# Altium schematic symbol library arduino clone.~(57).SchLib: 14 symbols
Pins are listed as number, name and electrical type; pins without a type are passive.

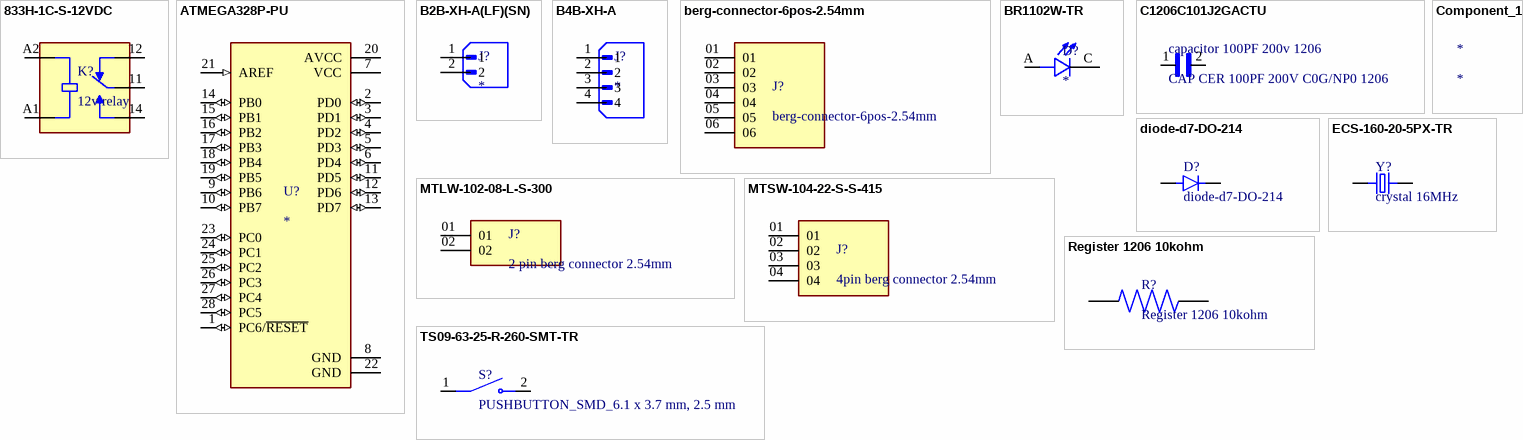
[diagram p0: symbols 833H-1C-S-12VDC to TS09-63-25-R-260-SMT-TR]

## 833H-1C-S-12VDC
designator K?, comment 12v relay
833H Series 10 A SPDT 12 VDC Through Hole Miniature Sugar Cube Power Relay; MF: Song Chuan; MP: 833H-1C-S-12VDC
footprint RELAY_833H-1C-S-12VDC
pins: 11 COM, 12 NC, 14 NO, A1 COIL2, A2 COIL1

## ATMEGA328P-PU
designator U?
ATmega Series 20 MHz 32 KB Flash 2 KB SRAM 8-Bit Microcontroller - DIP-28; MP: ATMEGA328P-PU
footprint Atmega328pU DIP Controller (Atmega328pU DIP)
pins: 1 PC6/~{RESET} (io), 2 PD0 (io), 3 PD1 (io), 4 PD2 (io), 5 PD3 (io), 6 PD4 (io), 7 VCC (power), 8 GND (power), 9 PB6 (io), 10 PB7 (io), 11 PD5 (io), 12 PD6 (io), 13 PD7 (io), 14 PB0 (io), 15 PB1 (io), 16 PB2 (io), 17 PB3 (io), 18 PB4 (io), 19 PB5 (io), 20 AVCC (power), 21 AREF (in), 22 GND (power), 23 PC0 (io), 24 PC1 (io), 25 PC2 (io), 26 PC3 (io), 27 PC4 (io), 28 PC5 (io)

## B2B-XH-A(LF)(SN)
designator J?
Connector Header Through Hole 2 position 0.098 (2.50mm); MF: JST Sales; MP: B2B-XH-A(LF)(SN)
footprint JST_B2B-XH-A(LF)(SN)
pins: 1, 2

## B4B-XH-A
designator J?
Connector Header Through Hole 4 position 0.098 (2.50mm); MF: JST Sales; MP: B4B-XH-A
footprint JST_B4B-XH-A
pins: 1, 2, 3, 4

## berg-connector-6pos-2.54mm
designator J?
MF: Samtec; MP: SSQ-106-02-G-S-LL
footprint berg-connector-6pin-2.54mm
pins: 01, 02, 03, 04, 05, 06

## BR1102W-TR
designator D?
LED Uni-Color Red 660nm 2-Pin SMD T/R; MP: BR1102W-TR
footprint LED_BR1102W-TR
pins: A, C

## C1206C101J2GACTU
designator capacitor 100PF 200v 1206, comment CAP CER 100PF 200V C0G/NP0 1206
MP: C1206C101J2GACTU
footprint capacitor 100nF 1206
pins: 1, 2

## Component_1
designator *

## diode-d7-DO-214
designator D?
MF: Diodes Inc.; MP: S1M-13-F
footprint diode-d7-DO-214
pins: A, C

## ECS-160-20-5PX-TR
designator Y?, comment crystal 16MHz
16 MHz Â±30ppm Crystal 20pF 40 Ohms HC-49/US; MF: ECS Inc.; MP: ECS-160-20-5PX-TR
footprint XTAL_ECS-160-20-5PX-TR
pins: 1, 2

## MTLW-102-08-L-S-300
designator J?, comment 2 pin berg connector 2.54mm
MP: MTLW-102-08-L-S-300
footprint SAMTEC_MTLW-102-08-L-S-300
pins: 01, 02

## MTSW-104-22-S-S-415
designator J?, comment 4pin berg connector 2.54mm
4 pin berg connector 2.54mm; MP: MTSW-104-22-S-S-415
footprint SAMTEC_MTSW-104-22-S-S-415
pins: 01, 02, 03, 04

## Register 1206 10kohm
designator R?
MP: RNCF1206BKY10K0
footprint RESC3015X65N (Register)
pins: 1, 2

## TS09-63-25-R-260-SMT-TR
designator S?, comment PUSHBUTTON_SMD_6.1 x 3.7 mm, 2.5 mm
6.1 x 3.7 mm, 2.5 mm Actuator Height, 260 gf, Red, Surface Mount, SPST, Tactile Switch; MF: Same Sky; MP: TS09-63-25-R-260-SMT-TR
footprint PUSHBUTTON_SMD_6.1 x 3.7 mm, 2.5 mm
pins: 1, 2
